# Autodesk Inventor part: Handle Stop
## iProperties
Shininess: 77.0
Length Units: 11269
Angle Units: 11279
Time Units: 11290
Mass Units: 11283
Length Display Precision: 3
Angle Display Precision: 2
Compacted: True
Created: 2002-02
Part Number: Handle Stop
Document SubType Name: Modeling
Designer: ***
Density: 1 g/cm^3
Density: 0.0
Volumn: 0.0
Area: 0.0
PropertySet Name: Model Information
Control State: 0
Master: False
Checked Out: False
Author: ***
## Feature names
1. Revolution1
